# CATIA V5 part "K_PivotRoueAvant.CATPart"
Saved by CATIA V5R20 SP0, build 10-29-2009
Part number: pivot_roue_avant
Publications: "Corps principal", "niveau de la roue avant", "hauteur roue avant", "ecart entre barres de soutien", "longueur des barres de soutien", "Surepaisseur du tube", "diamètre des barres", "Point.1", "Droite.2", "Point.4", "Point.5", "Droite.3", "Droite.4", "Plan.1", "Plan.2"
Bounding box of the stored display mesh (mm): x 640 to 850, y -300 to -100, z -100 to 50
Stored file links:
  G:\Khaled_CFAO_2011\ST2M\ST2M_GR1\cdurantin\cdurantin\Khaled\CAD_ThinkMOTION\K_PivotRoueAvant.CATPart
  G:\Khaled_CFAO_2011\ST2M\ST2M_GR1\cdurantin\cdurantin\Khaled\CAD_ThinkMOTION\K_Corps.CATPart
  G:\Khaled_CFAO_2011\ST2M\ST2M_GR1\cdurantin\cdurantin\CATIA\squelettecaddy.CATProduct
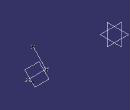
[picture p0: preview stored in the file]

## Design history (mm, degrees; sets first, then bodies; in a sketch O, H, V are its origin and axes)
External parameters (linked from other documents)
  `External.niveau de la roue avant` = 850 mm
  `External.hauteur roue avant` = 100 mm
  `External.ecart entre barres de soutien` = 600 mm
  `External.longueur des barres de soutien` = 800 mm
  `External.Surepaisseur du tube` = 10 mm
  `External.diamètre des barres` = 40 mm
Body1 (main body)
  Point1: (850 {= `External.niveau de la roue avant`}, -150 {= -`External.ecart entre barres de soutien` /2+`External.Surepaisseur du tube` +`External.diamètre des barres` +`External.hauteur roue avant`}, -100 {= -`External.hauteur roue avant`})
  Line1: type PtDir, RefPoint Point1, Direction zx-plane, Start 0, End 50
  Point2: (640 {= `External.longueur des barres de soutien` -`External.longueur des barres de soutien` /5}, -150 {= -`External.ecart entre barres de soutien` /2+`External.Surepaisseur du tube` +`External.diamètre des barres` +`External.hauteur roue avant`}, -100 {= -`External.hauteur roue avant`})
  Point3: (640, -300 {= -`External.ecart entre barres de soutien` /2}, 50 {= `External.diamètre des barres` +`External.Surepaisseur du tube`})
  Line2: type PtPt, FirstPoint Point2, SecondPoint Point1
  Line3: type PtPt, FirstPoint Point2, SecondPoint Point3
  Plane1: type 2Lines, Element1 Line2, Element2 Line3
  Plane2: type Angle, RefPlane Plane1, Direction Line2, Angle 90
